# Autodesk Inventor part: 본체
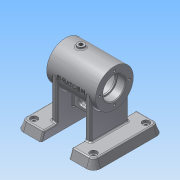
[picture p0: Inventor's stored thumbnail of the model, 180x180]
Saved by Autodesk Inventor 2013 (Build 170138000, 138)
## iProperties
Created: 2016-07
Part Number: 본체
Material: 알루미늄 6061
Document SubType Name: Modeling
Designer: Administrator
Mass: 499.462 g
Surface Area: 539.712 cm^2
Volume: 184.303 cm^3
Density: 2.71 g/cm^3
Author: Administrator
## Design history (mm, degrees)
sketch "스케치1"
  geometry: L1 (-40, 55)-(40, 55); L2 (40, -55)-(-40, -55); L3 (-50, 20)-(50, 20); L4 (-50, -20)-(50, -20); L5 (-50, -45)-(-50, -20); L6 (-50, 20)-(-50, 45); L7 (50, 45)-(50, 20); L8 (50, -20)-(50, -45); A1 r 10 centre (-40, -45) between (-50, -45) and (-40, -55); A2 r 10 centre (-40, 45) between (-40, 55) and (-50, 45); A3 r 10 centre (40, 45) between (50, 45) and (40, 55); A4 r 10 centre (40, -45) between (40, -55) and (50, -45); 7 further points
  constraints: 16 end point, 12 tangent, 8 point on circle, 6 perpendicular, 5 parallel, 4 centre point, 4 vertical alignment, 3 equal radius, 3 horizontal alignment, 3 point on line, 2 midpoint, 1 horizontal
  dimensions: "d3" = 10 radius of A1; "d4" = 35 distance between parallel lines of L3 L1; "d5" = 35 distance between parallel lines of L2 L4; "d6" = 100 distance between parallel lines of L7 L6; "d7" = 110 distance between parallel lines of L2 L1; "d8" = 20 distance from line of point (0, 0) L3; "d9" = 90 horizontal distance of A2.centre point (50, 55); "d10" = 80 distance of A4.centre A1.centre (derived); "d11" = 10 horizontal distance of A2.centre point (-50, 55); "d12" = 50 distance of point (0, 0) point (-50, 0); "d13" = 10 distance of L2.end point (-50, -55)
extrude "돌출1" new body sketch "스케치1" distance "d14" = 12; taper "d15" = 0 deg
feature "면 기울기1" dims angle "d16" = 20 deg
feature "면 기울기2" dims angle "d17" = 20 deg
sketch "스케치2"
  geometry: L1 (-50, 0)-(50, 0) reference; C1 r 27 at (0, 70); 1 further point
  constraints: 1 centre point, 1 vertical alignment
  dimensions: "d18" = 54 diameter of C1; "d20" = 70 distance from line of L1 C1.centre
extrude "돌출2" join sketch "스케치2" stored distance "d21" = 70; taper "d22" = 0 deg
node "작업 평면2"
sketch "스케치3"
  geometry: L1 (-50, 0)-(50, 0) reference; L2 (50, 0)-(45.632, 12) reference; L3 (-45.632, 12)-(45.632, 12) reference; L4 (-50, 0)-(-45.632, 12) reference; L5 (-27, 70)-(-27, 12); L6 (27, 70)-(27, 12); L7 (-27, 70)-(-24.953, 70); L8 (24.953, 70)-(27, 70); A1 r 27 centre (0, 70) between (-27, 70) and (27, 70) reference; A2 r 24.953 centre (0, 70) between (-24.953, 70) and (24.953, 70); 1 further point
  constraints: 8 end point, 4 point on circle, 3 perpendicular, 2 point on line, 2 tangent, 1 centre point, 1 collinear
  dimensions: "d24" = 24.9526 radius of A2
extrude "돌출3" join sketch "스케치3" distance "d26" = 8; taper "d27" = 0 deg
node "작업 평면3"
sketch "스케치4"
  geometry: L1 (40, 0)-(-40, 0) reference; L2 (-40, 0)-(-40, 12) reference; L3 (40, 12)-(-40, 12) reference; L4 (40, 0)-(40, 12) reference; L5 (-27, 70)-(-27, 12); L6 (27, 70)-(27, 12); L7 (-27, 70)-(-25.28, 70); L8 (27, 70)-(25.28, 70); A1 r 27 centre (0, 70) between (-27, 70) and (27, 70) reference; A2 r 25.28 centre (0, 70) between (-25.28, 70) and (25.28, 70); 1 further point
  constraints: 8 end point, 4 point on circle, 3 perpendicular, 2 point on line, 2 tangent, 1 centre point, 1 horizontal alignment
  dimensions: "d29" = 25.27997 radius of A2
extrude "돌출4" join sketch "스케치4" distance "d31" = 8; taper "d32" = 0 deg
sketch "스케치5"
  geometry: L1 (-35, 43)-(35, 43) reference; L2 (-20, 12)-(-20, 70) reference; L3 (20, 12)-(20, 70) reference; L4 (-20, 22)-(20, 22); L5 (-8, 35.5)-(8, 35.5); L6 (8, 28.5)-(-8, 28.5); L7 (20, 0)-(45, 0) reference; L8 (-20, 22)-(-20, 45.081); L9 (20, 45.081)-(20, 22); L10 (20, 45.081)-(-20, 45.081); A1 r 3.5 centre (8, 32) between (8, 28.5) and (8, 35.5); A2 r 3.5 centre (-8, 32) between (-8, 35.5) and (-8, 28.5); 3 further points
  constraints: 12 end point, 4 point on circle, 4 point on line, 4 tangent, 2 centre point, 2 midpoint, 2 parallel, 2 perpendicular, 2 vertical alignment, 1 collinear
  dimensions: "d33" = 21 distance between parallel lines of L4 L1; "d35" = 3.5 radius of A1; "d36" = 23 dimension on A1 A2; "d37" = 32 distance from line of L7 A1.centre; "d38" = 2.08082 distance between parallel lines of L1 L10
extrude "돌출5" join sketch "스케치5" stored distance "d39" = 8; taper "d40" = 0 deg
node "작업 평면4"
sketch "스케치6"
  geometry: L1 (-35, 27)-(-35, -27) reference; L2 (-20, -26.702)-(20, -26.702) reference; L3 (20, -26.702)-(20, 0) reference; L4 (20, 0)-(28, 0) reference; L5 (28, 0)-(28, 0) reference; L6 (20, 0)-(28, 0) reference; L7 (20, 0)-(20, -26.702) reference; L8 (20, -26.702)-(-20, -26.702) reference; L9 (-20, -26.702)-(-20, 0) reference; L10 (-28, 0)-(-20, 0) reference; L11 (-28, 0)-(-28, 0) reference; L12 (-28, 0)-(-20, 0) reference; L13 (-20, 0)-(-20, -26.702) reference; L14 (-35, 27)-(-35, -27) reference; L15 (35, -27)-(35, 27) reference; L16 (-35, 27)-(35, 27) reference; 2 further points
  constraints: 1 vertical alignment, 1 other
  dimensions: "d41" = 27 distance from line of point (0, 0) L16
feature "엠보싱1" sketch "스케치6" dims "d14" = 12, "d42" = 0.5, "d43" = 0
node "작업 평면5"
sketch "스케치7"
  geometry: L1 (-27, -35)-(27, -35) reference; C1 r 5 at (0, -13); 1 further point
  constraints: 1 centre point, 1 vertical alignment
  dimensions: "d45" = 22 distance from line of C1.centre L1; "d46" = 10 diameter of C1
extrude "돌출6" join sketch "스케치7" distance "d47" = 8; taper "d48" = 0 deg
sketch "스케치8"
  geometry: L1 (-35, 97)-(-35, 43) reference; L2 (35, 43)-(35, 97) reference; L3 (-35, 97)-(35, 97) reference; L4 (20, 43.298)-(-20, 43.298) reference; L5 (-35, 70)-(35, 70); L6 (-35, 86)-(-23, 86); L7 (-23, 86)-(-23, 84); L8 (-23, 84)-(-21, 84); L9 (-21, 84)-(-21, 92); L10 (-21, 92)-(21, 92); L11 (21, 92)-(21, 84); L12 (21, 84)-(23, 84); L13 (23, 84)-(23, 86); L14 (23, 86)-(35, 86); L15 (-35, 86)-(-35, 70); L16 (35, 86)-(35, 70); 1 further point
  constraints: 24 end point, 6 parallel, 4 collinear, 3 perpendicular, 2 horizontal alignment, 2 midpoint, 2 point on line, 1 vertical
  dimensions: "d49" = 27 distance between parallel lines of L5 L3; "d50" = 12 distance of L6.start L6.end; "d51" = 42 distance of L9.end L10.end; "d52" = 32 diameter of L6 L5; "d53" = 28 diameter of L8 L5; "d54" = 44 diameter of L10 L5
revolve "회전1" sketch "스케치8" stored, may be unused: angle "d55" = 90 deg
hole "구멍1" diameter "d58" = 5.188; stored, may be unused: countersink angle "d62" = 90 deg, drill point angle "d64" = 118 deg; dims "d56" = 10, "d57" = 10, "d59" = 10, "d60" = 4, "d61" = 2, "d63" = 10
sketch "스케치9"
  geometry: C1 r 16 at (0, 0) reference; C2 r 27 at (0, 0) reference; A1 r 21 centre (0, 0) between (0, 21) and (-21, 0); 3 further points
  constraints: 4 point on circle, 2 horizontal alignment, 2 vertical alignment, 1 centre point, 1 coincident
  dimensions: "d65" = 42 diameter of A1
hole "구멍2" sketch "스케치9" at (0, 21), (-21, 0), (21, 0), (0, -21) diameter "d66" = 3.459; stored, may be unused: countersink angle "d70" = 90 deg, drill point angle "d72" = 118 deg; dims "d67" = 8, "d68" = 4, "d69" = 2, "d71" = 10
node "작업 평면6"
sketch "스케치10"
  geometry: 5 further points
  constraints: 2 horizontal alignment, 2 vertical alignment
  dimensions: "d74" = 75 distance of point (37.5, 42.5) point (-37.5, 42.5); "d76" = 85 distance of point (-37.5, -42.5) point (-37.5, 42.5); "d77" = 42.5 vertical distance of point (0, 0) point (-37.5, 42.5); "d78" = 37.5 horizontal distance of point (0, 0) point (-37.5, 42.5)
hole "구멍3" sketch "스케치10" at (-37.5, 42.5), (37.5, 42.5), (-37.5, -42.5), (37.5, -42.5) diameter "d79" = 6; stored, may be unused: countersink angle "d83" = 90 deg, drill point angle "d85" = 118 deg; dims "d80" = 8, "d81" = 10, "d82" = 4, "d84" = 10
sketch "스케치11"
  geometry: L1 (0, 70)-(15.898, 44.559); L2 (0, 70)-(0, 43.298); L3 (20.986, 47.738)-(15.898, 44.559); L4 (20.986, 47.738)-(17.501, 53.316); C1 r 22 at (0, 70) reference; A1 r 24.179 centre (0, 70) between (12.813, 49.495) and (17.501, 53.316); 1 further point
  constraints: 8 end point, 2 point on circle, 2 point on line, 1 centre point, 1 perpendicular, 1 vertical
  dimensions: "d86" = 32 deg angle of L2 L1; "d87" = 30 distance of L1.start L1.end; "d90" = 24.17946 radius of A1; "d91" = 12 diameter of L4 L1; "d92" = 30 distance from line of L1.start L3
revolve "회전2" sketch "스케치11" stored, may be unused: angle "d93" = 90 deg
hole "구멍4" diameter "d96" = 5.188; stored, may be unused: countersink angle "d100" = 90 deg, drill point angle "d102" = 118 deg; dims "d94" = 10, "d95" = 10, "d97" = 10, "d98" = 10, "d99" = 4, "d101" = 10
chamfer "모따기1" distance "d103" = 1; stored, may be unused: second distance "d104" = 2, angle "d105" = 45 deg
fillet "모깎기3" dims "d108" = 2
fillet "모깎기4" dims "d109" = 2
fillet "모깎기5" dims "d110" = 2
fillet "모깎기6" dims "d111" = 3
fillet "모깎기7" dims "d112" = 0.3
fillet "모깎기8" dims "d113" = 2
fillet "모깎기9" dims "d114" = 2
fillet "모깎기10" dims "d115" = 2
fillet "모깎기11" dims "d116" = 2
fillet "모깎기12" dims "d117" = 2
fillet "모깎기13" dims "d118" = 2
fillet "모깎기14" dims "d119" = 2
node "솔리드1"
mirror "대칭1"
node "투영된 루프1"
node "투영된 루프2"
node "투영된 루프3"
node "투영된 루프4"
node "투영된 루프5"
other parameters: "d73" = 12, "d89" = 12
